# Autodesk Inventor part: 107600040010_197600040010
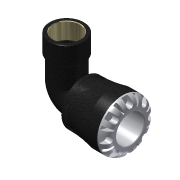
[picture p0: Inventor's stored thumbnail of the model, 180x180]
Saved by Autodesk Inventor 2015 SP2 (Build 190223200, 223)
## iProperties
Created: 2016-12
Part Number: 107600040010_197600040010
Material: PVC-Piping
Description: PLASSON 90° ELBOW WITH FEMALE INTEGRAL BRASS 40X1" SERIES 1
Document SubType Name: Modeling
Designer: KIM
Mass: 664.223 g
Surface Area: 733.008 cm^2
Volume: 474.445 cm^3
Density: 1.4 g/cm^3
Appearance: Black Cast
Author: KIM
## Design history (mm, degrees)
derived "1076.ipt"
feature "Solid1::1076.ipt"
tag "TaggingFeature1"
body "Solid1"
other parameters: "d1" = 30.24, "d8" = 61.6, "d13" = 8, "d14" = 8, "d15" = 0, "d17" = 360 deg, "d19" = 8 deg, "d20" = 0.8, "d21" = 0.8, "d22" = 8 deg, "d24" = 0, "d26" = 360 deg, "d33" = 7, "d51" = 0.7, "d54" = 14, "d55" = 8.8, "d57" = 15.68, "d58" = 0, "d74" = 0, "d78" = 72, "d82" = 0.8, "d115" = 360 deg, "d207" = 90 deg, "d228" = 11.9, "d248" = 4.32, "d270" = 107, "d281" = 4.54365, "d294" = 30.291, "d295" = 19, "d296" = 20.9, "d297" = 27.2619, "d299" = 35.44047, "d300" = 27.2619, "d301" = 0, "d302" = 0, "d306" = 1.96891, "d309" = 72.72, "d310" = 13.07977, "d312" = 15 deg, "d313" = 0.56, "d314" = 8.208, "d315" = 0.35, "l_" = 72, "A_" = 107, "l_2" = 19, "Rp_" = 30.291, "d9" = 10, "d298" = 39.3783
